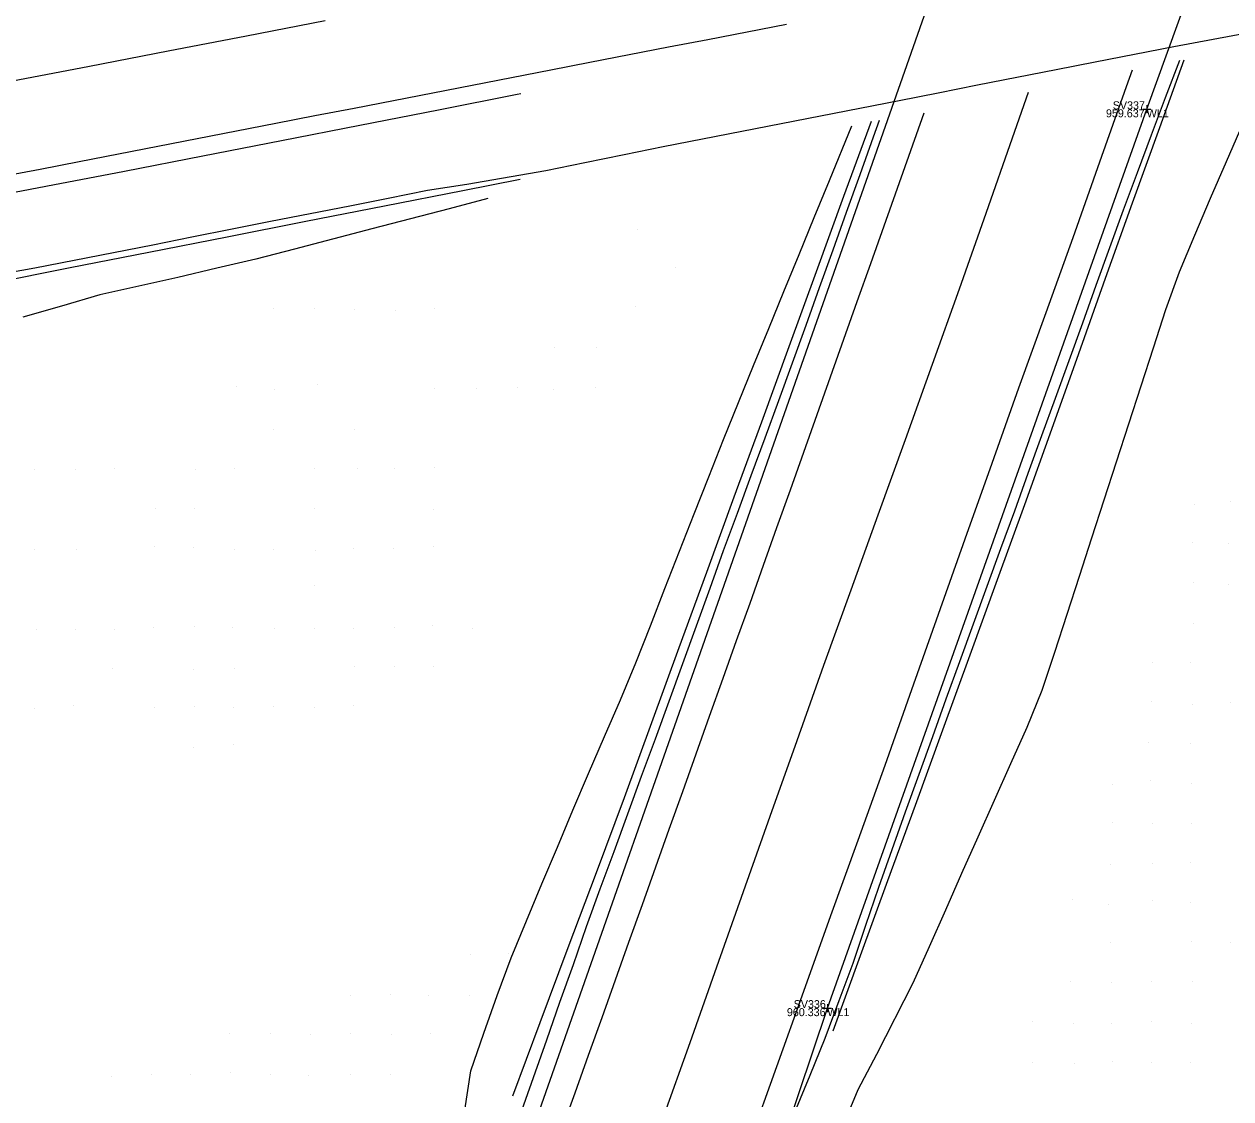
# Model space of a CAD drawing. Extents: x 2262025 to 2264532, y 740981 to 742724.
# Drawn here: x 2263077.7 to 2263228.5, y 741908.8 to 742043.1 of the extents above; entities that cross this region are included whole.
import ezdxf

# ---------------------------------------------------------------- set-up
doc = ezdxf.new("R2010")
doc.units = 0
for name, color, linetype in [('GE_X_Alignment_1000_Curve_Data', 7, 'Continuous'), ('GE_X_Alignment_100_Bearings', 7, 'Continuous'), ('GE_X_Alignment_100_Curve_Data', 7, 'Continuous'), ('Ground Shots', 7, 'Continuous'), ('HY_X_Spring_Cells', 7, 'Continuous'), ('RW_X_CL', 7, 'Continuous'), ('RW_X_CL_1000_Distances', 7, 'Continuous'), ('RW_X_CL_100_Cardinal_Points', 7, 'Continuous'), ('SC_Scratch2', 7, 'Continuous'), ('SC_Scratch4', 7, 'Continuous'), ('SV_X_Control_Cells_Found', 7, 'Continuous'), ('SV_X_Text_Comment', 7, 'Continuous'), ('UT_X_Gas', 7, 'Continuous'), ('UT_X_Water', 7, 'Continuous')]:
    doc.layers.add(name, color=color, linetype=linetype)

msp = doc.modelspace()

# ---------------------------------------------------------------- linework, layer by layer
at = {"layer": 'GE_X_Alignment_1000_Curve_Data'}
msp.add_lwpolyline([(2263021.48, 742011.61), (2263031.3, 742013.49), (2263041.12, 742015.37), (2263050.94, 742017.25), (2263060.76, 742019.14), (2263070.58, 742021.02), (2263080.41, 742022.9), (2263090.23, 742024.78), (2263100.05, 742026.67), (2263109.86, 742028.59), (2263119.67, 742030.51), (2263129.49, 742032.44), (2263139.3, 742034.36), (2263139.77, 742034.45)], dxfattribs=at)
at = {"layer": 'GE_X_Alignment_100_Bearings'}
for points in [[(2263178.8, 741917.36), (2263182.22, 741926.75), (2263185.64, 741936.15), (2263189.06, 741945.55), (2263192.48, 741954.94), (2263195.9, 741964.34), (2263199.32, 741973.74), (2263202.74, 741983.13), (2263206.13, 741992.54), (2263209.48, 742001.96), (2263212.83, 742011.39), (2263216.2, 742020.8), (2263219.59, 742030.21), (2263222.64, 742038.67)], [(2263183.53, 742030.98), (2263180.1, 742021.59), (2263176.67, 742012.2), (2263173.24, 742002.8), (2263169.82, 741993.41), (2263166.39, 741984.01), (2263162.96, 741974.62), (2263159.53, 741965.22), (2263156.11, 741955.83), (2263152.66, 741946.44), (2263149.16, 741937.08), (2263145.66, 741927.71), (2263142.16, 741918.34), (2263138.74, 741909.2)], [(2262916.55, 741980.49), (2262926.37, 741982.37), (2262936.2, 741984.25), (2262946.02, 741986.13), (2262955.84, 741988.01), (2262965.66, 741989.9), (2262975.48, 741991.78), (2262985.3, 741993.66), (2262995.12, 741995.54), (2263004.94, 741997.43), (2263014.77, 741999.31), (2263024.59, 742001.19), (2263034.41, 742003.07), (2263044.22, 742004.98), (2263054.04, 742006.91), (2263063.85, 742008.84), (2263073.66, 742010.78), (2263083.47, 742012.71), (2263093.28, 742014.64), (2263103.09, 742016.57), (2263112.91, 742018.5), (2263122.72, 742020.43), (2263132.53, 742022.36), (2263139.69, 742023.77)]]:
    msp.add_lwpolyline(points, dxfattribs=at)
at = {"layer": 'GE_X_Alignment_100_Curve_Data'}
for points in [[(2263231.19, 742042.14), (2263226.28, 742041.21), (2263221.36, 742040.28), (2263216.45, 742039.35), (2263211.54, 742038.39), (2263206.64, 742037.43), (2263201.73, 742036.46), (2263196.83, 742035.49), (2263191.92, 742034.52), (2263187.02, 742033.54), (2263182.11, 742032.58), (2263177.2, 742031.63), (2263172.3, 742030.67), (2263167.39, 742029.72), (2263162.48, 742028.76), (2263157.57, 742027.81), (2263152.68, 742026.8), (2263147.78, 742025.79), (2263142.88, 742024.8), (2263133, 742023.08), (2263128.1, 742022.34), (2263123.2, 742021.35), (2263118.39, 742020.38), (2263113.44, 742019.42), (2263108.48, 742018.46), (2263103.69, 742017.51), (2263098.67, 742016.52), (2263093.77, 742015.53), (2263088.87, 742014.55), (2263083.96, 742013.59), (2263079.05, 742012.65), (2263074.13, 742011.78)], [(2263222.05, 742038.6), (2263220.29, 742033.93), (2263218.52, 742029.25), (2263216.78, 742024.56), (2263215.04, 742019.87), (2263213.34, 742015.18), (2263211.63, 742010.48), (2263209.93, 742005.78), (2263208.22, 742001.07), (2263206.52, 741996.37), (2263204.82, 741991.67), (2263203.13, 741986.97), (2263201.43, 741982.26), (2263199.72, 741977.57), (2263198.01, 741972.87), (2263196.29, 741968.17), (2263194.58, 741963.47), (2263192.88, 741958.77), (2263191.19, 741954.07), (2263189.49, 741949.36), (2263187.8, 741944.66), (2263186.13, 741939.95), (2263184.45, 741935.24), (2263182.85, 741930.5), (2263181.24, 741925.77), (2263179.5, 741921.08), (2263177.75, 741916.4), (2263175.86, 741911.77), (2263173.98, 741907.14)], [(2263139.68, 741906.79), (2263141.34, 741911.51), (2263143, 741916.22), (2263144.66, 741920.94), (2263146.33, 741925.65), (2263147.99, 741930.37), (2263149.68, 741935.08), (2263151.41, 741939.77), (2263153.14, 741944.46), (2263154.86, 741949.15), (2263156.59, 741953.84), (2263158.31, 741958.54), (2263160.01, 741963.24), (2263161.71, 741967.94), (2263163.41, 741972.64), (2263165.11, 741977.35), (2263166.83, 741982.04), (2263168.55, 741986.74), (2263170.28, 741991.43), (2263172.01, 741996.12), (2263173.7, 742000.82), (2263175.4, 742005.53), (2263177.09, 742010.23), (2263178.78, 742014.94), (2263180.47, 742019.64), (2263182.16, 742024.35), (2263183.85, 742029.06), (2263184.59, 742031.12)]]:
    msp.add_lwpolyline(points, dxfattribs=at)
at = {"layer": 'Ground Shots'}
for p, q in [((2263154.3, 742017.45), (2263154.3, 742017.45)), ((2263159.13, 742012.71), (2263159.13, 742012.71)), ((2263108.92, 742007.6), (2263108.92, 742007.6)), ((2263114, 742007.63), (2263114, 742007.63)), ((2263154.04, 742007.85), (2263154.04, 742007.85)), ((2263118.96, 742007.53), (2263118.96, 742007.53)), ((2263124.15, 742007.38), (2263124.15, 742007.38)), ((2263129.01, 742007.59), (2263129.01, 742007.59)), ((2263144.02, 742002.7), (2263144.02, 742002.7)), ((2263149.2, 742002.68), (2263149.2, 742002.68)), ((2263104.19, 741997.85), (2263104.19, 741997.85)), ((2263109.03, 741997.43), (2263109.03, 741997.43)), ((2263114.32, 741998.07), (2263114.32, 741998.07)), ((2263128.94, 741997.59), (2263128.94, 741997.59)), ((2263134.18, 741997.58), (2263134.18, 741997.58)), ((2263139.31, 741997.69), (2263139.31, 741997.69)), ((2263143.81, 741997.47), (2263143.81, 741997.47)), ((2263149.07, 741997.67), (2263149.07, 741997.67)), ((2263108.9, 741992.52), (2263108.9, 741992.52)), ((2263118.93, 741992.47), (2263118.93, 741992.47)), ((2263079.01, 741987.54), (2263079.01, 741987.54)), ((2263084.09, 741987.46), (2263084.09, 741987.46)), ((2263089.03, 741987.55), (2263089.03, 741987.55)), ((2263099.06, 741987.49), (2263099.06, 741987.49)), ((2263103.96, 741987.57), (2263103.96, 741987.57)), ((2263114, 741987.62), (2263114, 741987.62)), ((2263119.3, 741987.59), (2263119.3, 741987.59)), ((2263123.95, 741987.56), (2263123.95, 741987.56)), ((2263128.98, 741987.69), (2263128.98, 741987.69)), ((2263094.16, 741982.62), (2263094.16, 741982.62)), ((2263098.95, 741982.66), (2263098.95, 741982.66)), ((2263113.99, 741982.57), (2263113.99, 741982.57)), ((2263128.88, 741982.46), (2263128.88, 741982.46)), ((2263223.93, 741983.08), (2263223.93, 741983.08)), ((2263228.46, 741983.47), (2263228.46, 741983.47)), ((2263078.99, 741977.53), (2263078.99, 741977.53)), ((2263084.23, 741977.55), (2263084.23, 741977.55)), ((2263094.05, 741977.82), (2263094.05, 741977.82)), ((2263098.92, 741977.69), (2263098.92, 741977.69)), ((2263104.04, 741977.46), (2263104.04, 741977.46)), ((2263108.91, 741977.45), (2263108.91, 741977.45)), ((2263118.8, 741977.59), (2263118.8, 741977.59)), ((2263123.81, 741977.57), (2263123.81, 741977.57)), ((2263128.84, 741977.81), (2263128.84, 741977.81)), ((2263223.69, 741978.38), (2263223.69, 741978.38)), ((2263228.18, 741978.3), (2263228.18, 741978.3)), ((2263114.1, 741977.42), (2263114.1, 741977.42)), ((2263114, 741972.96), (2263114, 741972.96)), ((2263223.83, 741973.37), (2263223.83, 741973.37)), ((2263228.2, 741973.12), (2263228.2, 741973.12)), ((2263079.26, 741967.52), (2263079.26, 741967.52)), ((2263084.1, 741967.43), (2263084.1, 741967.43)), ((2263088.94, 741967.51), (2263088.94, 741967.51)), ((2263093.83, 741967.73), (2263093.83, 741967.73)), ((2263099.04, 741967.91), (2263099.04, 741967.91)), ((2263103.77, 741967.77), (2263103.77, 741967.77)), ((2263109.01, 741967.67), (2263109.01, 741967.67)), ((2263113.99, 741967.57), (2263113.99, 741967.57)), ((2263118.9, 741967.62), (2263118.9, 741967.62)), ((2263123.98, 741967.7), (2263123.98, 741967.7)), ((2263128.68, 741968.05), (2263128.68, 741968.05)), ((2263133.75, 741967.62), (2263133.75, 741967.62)), ((2263223.82, 741968.24), (2263223.82, 741968.24)), ((2263088.79, 741962.6), (2263088.79, 741962.6)), ((2263098.87, 741962.5), (2263098.87, 741962.5)), ((2263104, 741962.63), (2263104, 741962.63)), ((2263118.95, 741962.83), (2263118.95, 741962.83)), ((2263123.95, 741962.92), (2263123.95, 741962.92)), ((2263128.86, 741962.9), (2263128.86, 741962.9)), ((2263218.64, 741963.41), (2263218.64, 741963.41)), ((2263223.47, 741963.38), (2263223.47, 741963.38)), ((2263083.89, 741957.98), (2263083.89, 741957.98)), ((2263098.94, 741957.87), (2263098.94, 741957.87)), ((2263108.86, 741957.91), (2263108.86, 741957.91)), ((2263118.83, 741958), (2263118.83, 741958)), ((2263218.63, 741958.49), (2263218.63, 741958.49)), ((2263223.7, 741958.13), (2263223.7, 741958.13)), ((2263228.4, 741958.39), (2263228.4, 741958.39)), ((2263078.98, 741957.57), (2263078.98, 741957.57)), ((2263093.96, 741957.72), (2263093.96, 741957.72)), ((2263103.86, 741957.76), (2263103.86, 741957.76)), ((2263113.93, 741957.74), (2263113.93, 741957.74)), ((2263218.17, 741953.32), (2263218.17, 741953.32)), ((2263098.9, 741952.78), (2263098.9, 741952.78)), ((2263103.84, 741953.12), (2263103.84, 741953.12)), ((2263223.41, 741953.26), (2263223.41, 741953.26)), ((2263213.65, 741948.08), (2263213.65, 741948.08)), ((2263218.49, 741948.61), (2263218.49, 741948.61)), ((2263223.58, 741948.31), (2263223.58, 741948.31)), ((2263213.72, 741943.39), (2263213.72, 741943.39)), ((2263218.75, 741943.23), (2263218.75, 741943.23)), ((2263223.6, 741943.3), (2263223.6, 741943.3)), ((2263218.65, 741938.26), (2263218.65, 741938.26)), ((2263223.4, 741938.4), (2263223.4, 741938.4)), ((2263213.47, 741938.16), (2263213.47, 741938.16)), ((2263208.74, 741933.71), (2263208.74, 741933.71)), ((2263213.21, 741933.1), (2263213.21, 741933.1)), ((2263218.69, 741933.58), (2263218.69, 741933.58)), ((2263223.49, 741933.33), (2263223.49, 741933.33)), ((2263213.41, 741928.33), (2263213.41, 741928.33)), ((2263223.59, 741928.51), (2263223.59, 741928.51)), ((2263228.44, 741928.39), (2263228.44, 741928.39)), ((2263133.44, 741926.91), (2263133.44, 741926.91)), ((2263138.21, 741926.98), (2263138.21, 741926.98)), ((2263208.47, 741923.54), (2263208.47, 741923.54)), ((2263213.53, 741923.44), (2263213.53, 741923.44)), ((2263218.51, 741923.53), (2263218.51, 741923.53)), ((2263223.64, 741923.45), (2263223.64, 741923.45)), ((2263118.52, 741921.82), (2263118.52, 741921.82)), ((2263123.53, 741921.84), (2263123.53, 741921.84)), ((2263128.18, 741921.74), (2263128.18, 741921.74)), ((2263133.36, 741921.82), (2263133.36, 741921.82)), ((2263203.68, 741918.46), (2263203.68, 741918.46)), ((2263208.84, 741918.21), (2263208.84, 741918.21)), ((2263213.53, 741918.22), (2263213.53, 741918.22)), ((2263218.53, 741918.5), (2263218.53, 741918.5)), ((2263223.53, 741918.29), (2263223.53, 741918.29)), ((2263103.41, 741916.98), (2263103.41, 741916.98)), ((2263108.48, 741916.96), (2263108.48, 741916.96)), ((2263113.52, 741916.83), (2263113.52, 741916.83)), ((2263118.53, 741916.97), (2263118.53, 741916.97)), ((2263123.55, 741916.84), (2263123.55, 741916.84)), ((2263128.49, 741916.99), (2263128.49, 741916.99)), ((2263203.64, 741913.42), (2263203.64, 741913.42)), ((2263208.93, 741913.3), (2263208.93, 741913.3)), ((2263213.64, 741913.47), (2263213.64, 741913.47)), ((2263218.53, 741913.43), (2263218.53, 741913.43)), ((2263223.47, 741913.42), (2263223.47, 741913.42)), ((2263088.58, 741911.62), (2263088.58, 741911.62)), ((2263093.58, 741911.93), (2263093.58, 741911.93)), ((2263098.52, 741911.86), (2263098.52, 741911.86)), ((2263103.52, 741912.15), (2263103.52, 741912.15)), ((2263108.52, 741911.89), (2263108.52, 741911.89)), ((2263113.26, 741911.76), (2263113.26, 741911.76)), ((2263118.45, 741911.9), (2263118.45, 741911.9)), ((2263123.49, 741911.89), (2263123.49, 741911.89))]:
    msp.add_line(p, q, dxfattribs=at)
at = {"layer": 'RW_X_CL_1000_Distances'}
for points in [[(2263074.78, 742024.08), (2263079.69, 742025.03), (2263084.59, 742025.98), (2263089.5, 742026.94), (2263094.41, 742027.89), (2263099.32, 742028.84), (2263104.23, 742029.8), (2263109.14, 742030.75), (2263114.04, 742031.7), (2263118.95, 742032.65), (2263123.86, 742033.61), (2263128.77, 742034.56), (2263133.68, 742035.51), (2263138.59, 742036.46), (2263143.5, 742037.42), (2263148.4, 742038.37), (2263153.31, 742039.32), (2263158.22, 742040.28), (2263163.13, 742041.23), (2263168.04, 742042.18), (2263172.95, 742043.13)], [(2263144.07, 741827.33), (2263146.5, 741837.03), (2263149.17, 741846.66), (2263152.19, 741856.2), (2263155.25, 741865.72), (2263158.43, 741875.2), (2263161.74, 741884.64), (2263165.04, 741894.07), (2263168.4, 741903.49), (2263171.77, 741912.91), (2263175.14, 741922.32), (2263178.52, 741931.74), (2263181.9, 741941.15), (2263185.27, 741950.56), (2263188.61, 741959.99), (2263191.96, 741969.41), (2263195.3, 741978.83), (2263198.65, 741988.26), (2263202.01, 741997.67), (2263205.4, 742007.08), (2263208.8, 742016.49), (2263212.12, 742025.92), (2263215.45, 742035.35), (2263216.18, 742037.41)], [(2263190.12, 742032.02), (2263188.45, 742027.3), (2263186.78, 742022.59), (2263185.11, 742017.88), (2263183.44, 742013.17), (2263181.77, 742008.45), (2263180.1, 742003.74), (2263178.43, 741999.03), (2263176.76, 741994.31), (2263175.09, 741989.6), (2263173.41, 741984.89), (2263171.73, 741980.18), (2263170.05, 741975.47), (2263168.37, 741970.76), (2263166.69, 741966.06), (2263165, 741961.35), (2263163.32, 741956.64), (2263161.64, 741951.93), (2263159.96, 741947.22), (2263158.28, 741942.51), (2263156.59, 741937.8), (2263154.91, 741933.1), (2263153.23, 741928.39), (2263151.55, 741923.68), (2263149.87, 741918.97), (2263148.18, 741914.26), (2263146.5, 741909.55), (2263144.82, 741904.84)]]:
    msp.add_lwpolyline(points, dxfattribs=at)
at = {"layer": 'RW_X_CL_100_Cardinal_Points'}
for p, q in [((2263217.48, 742032.49), (2263218.48, 742032.49)), ((2263217.98, 742032.99), (2263217.98, 742031.99)), ((2263217.98, 742032.49), (2263217.98, 742032.49)), ((2263177.57, 741920.18), (2263178.57, 741920.18)), ((2263178.07, 741920.68), (2263178.07, 741919.68)), ((2263178.07, 741920.18), (2263178.07, 741920.18))]:
    msp.add_line(p, q, dxfattribs=at)
at = {"layer": 'SC_Scratch2'}
msp.add_lwpolyline([(2262918.97, 742005.55), (2262928.79, 742007.46), (2262938.6, 742009.37), (2262948.42, 742011.29), (2262958.23, 742013.2), (2262968.05, 742015.12), (2262977.86, 742017.03), (2262987.68, 742018.94), (2262997.5, 742020.86), (2263007.31, 742022.75), (2263017.13, 742024.65), (2263026.95, 742026.54), (2263036.77, 742028.44), (2263046.59, 742030.33), (2263056.41, 742032.22), (2263066.23, 742034.12), (2263076.05, 742036.01), (2263085.87, 742037.9), (2263095.69, 742039.8), (2263105.5, 742041.69), (2263115.32, 742043.59)], dxfattribs=at)
at = {"layer": 'SC_Scratch4'}
msp.add_lwpolyline([(2263130.7, 741831.13), (2263134.04, 741840.55), (2263137.38, 741849.98), (2263140.73, 741859.4), (2263144.07, 741868.83), (2263147.42, 741878.25), (2263150.8, 741887.66), (2263154.17, 741897.08), (2263157.55, 741906.49), (2263160.93, 741915.9), (2263164.27, 741925.33), (2263167.6, 741934.75), (2263170.94, 741944.18), (2263174.28, 741953.61), (2263177.64, 741963.03), (2263181.03, 741972.43), (2263184.42, 741981.84), (2263187.82, 741991.25), (2263191.21, 742000.65), (2263194.57, 742010.07), (2263197.89, 742019.5), (2263201.21, 742028.94), (2263203.22, 742034.64)], dxfattribs=at)
at = {"layer": 'SV_X_Control_Cells_Found'}
for points in [[(2263178.09, 741900.8), (2263181.93, 741910.02), (2263184.27, 741914.44), (2263188.79, 741923.34), (2263190.83, 741927.9), (2263192.86, 741932.47), (2263194.89, 741937.03), (2263196.92, 741941.6), (2263198.95, 741946.16), (2263200.99, 741950.73), (2263203.02, 741955.29), (2263204.89, 741959.92), (2263206.5, 741964.66), (2263209.58, 741974.17), (2263211.12, 741978.93), (2263212.66, 741983.68), (2263214.21, 741988.44), (2263215.75, 741993.19), (2263217.29, 741997.95), (2263218.83, 742002.7), (2263220.37, 742007.46), (2263222.05, 742012.17), (2263223.97, 742016.78), (2263225.96, 742021.37), (2263227.94, 742025.95), (2263233.88, 742039.67)], [(2263132.76, 741907.45), (2263133.51, 741912.35), (2263135.16, 741917.07), (2263136.82, 741921.78), (2263138.57, 741926.46), (2263140.49, 741931.08), (2263142.41, 741935.7), (2263144.34, 741940.31), (2263146.27, 741944.92), (2263148.24, 741949.52), (2263150.22, 741954.11), (2263152.2, 741958.7), (2263154.13, 741963.31), (2263155.95, 741967.96), (2263157.78, 741972.62), (2263159.6, 741977.27), (2263161.43, 741981.93), (2263163.26, 741986.58), (2263165.09, 741991.23), (2263166.95, 741995.86), (2263168.85, 742000.48), (2263170.74, 742005.11), (2263172.64, 742009.73), (2263174.53, 742014.36), (2263176.43, 742018.99), (2263178.32, 742023.61), (2263181.11, 742030.42)], [(2263135.64, 742021.33), (2263130.81, 742020.07), (2263125.97, 742018.81), (2263121.13, 742017.55), (2263111.47, 742015.03), (2263106.65, 742013.78), (2263101.78, 742012.63), (2263096.92, 742011.49), (2263092.04, 742010.4), (2263087.16, 742009.3), (2263082.36, 742007.91), (2263077.56, 742006.52)]]:
    msp.add_lwpolyline(points, dxfattribs=at)
at = {"layer": 'UT_X_Gas'}
msp.add_lwpolyline([(2263370.65, 742558.56), (2263358.32, 742523.53), (2263332.75, 742449.83), (2263131.85, 741878.34), (2263108.26, 741811.62)], dxfattribs=at)
at = {"layer": 'UT_X_Water'}
msp.add_lwpolyline([(2263058.18, 741572.97), (2263085.82, 741651.25), (2263095.93, 741679.99), (2263097.95, 741685.82), (2263106.82, 741712.78), (2263147.36, 741828.66), (2263178.07, 741920.18), (2263217.98, 742032.49), (2263252.6, 742127.99), (2263295.63, 742247.6), (2263334.95, 742356.22), (2263370.78, 742449.55), (2263413.67, 742573.04), (2263421.38, 742593.43)], dxfattribs=at)

# ---------------------------------------------------------------- texts
at = {"layer": 'HY_X_Spring_Cells'}
for s, p in [('959.637', (2263212.88, 742031.49)), ('960.336', (2263173.01, 741919.18))]:
    msp.add_text(s, height=1, dxfattribs=at).set_placement(p)
at = {"layer": 'RW_X_CL'}
for p in [(2263217.98, 742031.49), (2263178.07, 741919.18)]:
    msp.add_text('WL1', height=1, dxfattribs=at).set_placement(p)
at = {"layer": 'SV_X_Text_Comment'}
for s, p in [('SV337', (2263213.73, 742032.49)), ('SV336', (2263173.86, 741920.18))]:
    msp.add_text(s, height=1, dxfattribs=at).set_placement(p)

doc.saveas('drawing.dxf')
